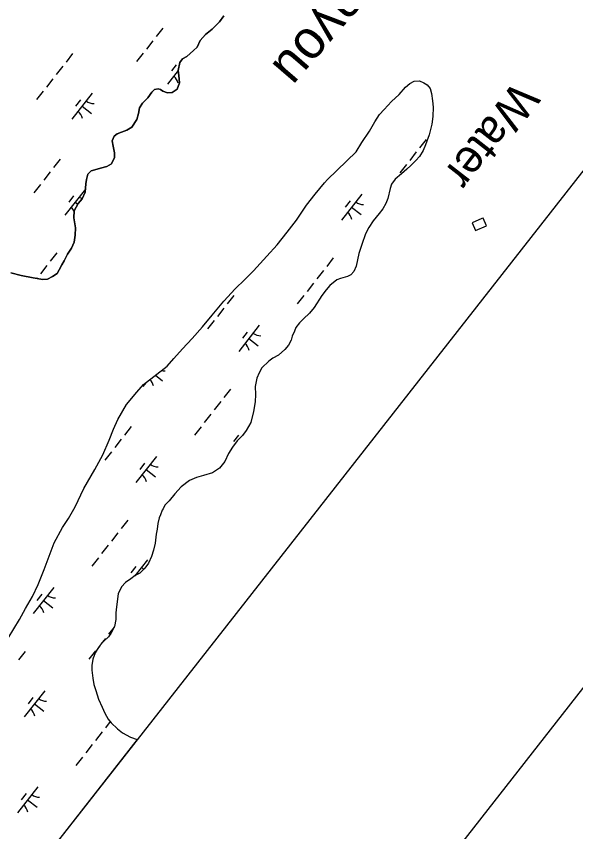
# Model space of a CAD drawing. Extents: x 3896831 to 3918110, y 171006 to 193349.
# Drawn here: x 3906732 to 3907575, y 172821 to 174050 of the extents above; entities that cross this region are included whole.
import ezdxf

# ---------------------------------------------------------------- set-up
doc = ezdxf.new("R2010")
doc.units = 0
for name, color, linetype in [('V-ANNO-SYMB', 7, 'Continuous'), ('V-CHAN-DOCK', 7, 'Continuous'), ('V-GRID-FRAM', 7, 'Continuous'), ('V-RIVR-IDEN', 7, 'Continuous'), ('V-TOPO-SHOR', 7, 'Continuous'), ('V-WETL-SWMP', 7, 'Continuous')]:
    doc.layers.add(name, color=color, linetype=linetype)

msp = doc.modelspace()

# ---------------------------------------------------------------- linework, layer by layer
at = {"layer": 'V-ANNO-SYMB'}
msp.add_lwpolyline([(3907767.9, 191844.4), (3897563.8, 178825.1), (3906582.3, 171756.8), (3916786.3, 184776.1), (3907767.9, 191844.4)], dxfattribs=at)
at = {"layer": 'V-CHAN-DOCK'}
msp.add_lwpolyline([(3907433.8, 173745), (3907419.1, 173738.7), (3907424.1, 173726.9), (3907440.7, 173734), (3907435.7, 173745.8)], close=True, dxfattribs=at)
at = {"layer": 'V-GRID-FRAM'}
msp.add_lwpolyline([(3916044.9, 184610), (3906752.8, 172754.1), (3900055.1, 177809.8), (3909313.3, 189695.8), (3916044.9, 184610)], dxfattribs=at)
at = {"layer": 'V-TOPO-SHOR'}
for points in [[(3906890.5, 173875.2), (3906898.4, 173878), (3906906.3, 173882.9), (3906913.8, 173894.5), (3906916.4, 173903.2), (3906917.9, 173912), (3906922.2, 173918.8), (3906930.1, 173927.2), (3906936.4, 173935.6), (3906940.3, 173939.6), (3906945.9, 173940.5), (3906949.4, 173939.3), (3906953, 173937), (3906959.8, 173934.3), (3906967, 173935.2), (3906974.5, 173940), (3906977.9, 173949.6), (3906977, 173960.7), (3906976.1, 173968.2), (3906978.4, 173980.2), (3906982.7, 173985.8), (3906989, 173989), (3906999.3, 173998.3), (3907004.4, 174003.1), (3907009, 174013.5), (3907017.3, 174022.3), (3907027.1, 174030.3), (3907038.5, 174041.6), (3907044.8, 174050.4)], [(3906898.2, 173464.9), (3906913.8, 173483.7), (3906924, 173495.3), (3906943.6, 173510.5), (3906959.3, 173522.9), (3906969.5, 173534.5), (3906982.4, 173548.9), (3906996.9, 173564.5), (3907012.9, 173582.1), (3907027.4, 173599.3), (3907044.6, 173620.8), (3907061.8, 173639.2), (3907076.3, 173653.2), (3907089.6, 173666.4), (3907109.6, 173688.4), (3907125.2, 173705.6), (3907140.5, 173724.4), (3907154.5, 173742.7), (3907169.3, 173765.1), (3907182.6, 173781.8), (3907196.7, 173799), (3907201, 173803.8), (3907244.1, 173845.4), (3907252.7, 173859.8), (3907264.4, 173876.5), (3907272.5, 173890.8), (3907279.6, 173902), (3907286.2, 173909.6), (3907297.6, 173921.2), (3907308.9, 173932), (3907318.7, 173943.2), (3907325, 173948.8), (3907331.7, 173952), (3907339.6, 173952.5), (3907346.4, 173949.8), (3907351.5, 173946.3), (3907355.9, 173941.2), (3907358, 173933.3), (3907359.3, 173922.6), (3907360.2, 173912.7), (3907360, 173898.9), (3907358.5, 173887.4), (3907354.3, 173871.1), (3907348.9, 173856.4), (3907345.4, 173847.7), (3907339.6, 173838.5), (3907334.1, 173832.5), (3907326.7, 173824.9), (3907320.8, 173819.7), (3907312.6, 173812.5), (3907303.1, 173804.5), (3907297.3, 173796.9), (3907295.4, 173790.5), (3907292, 173775.4), (3907288.9, 173767.9), (3907284.6, 173759.5), (3907279.1, 173752.7), (3907269.8, 173741.6), (3907263.1, 173731.6), (3907258.1, 173722), (3907252.7, 173705.8), (3907248.5, 173692.6), (3907246.2, 173682.7), (3907244.3, 173673.6), (3907240.9, 173665.2), (3907236.2, 173660.1), (3907231, 173658), (3907220.8, 173654.7), (3907214.9, 173652.7), (3907204.7, 173644.3), (3907199.2, 173637.9), (3907192.6, 173629.1), (3907180.9, 173611.2), (3907173.8, 173602.4), (3907164.8, 173594), (3907158.9, 173588), (3907153.5, 173581.2), (3907151.1, 173575.6), (3907147.7, 173568.1), (3907146.1, 173562.1), (3907142.3, 173554.6), (3907136.8, 173547.8), (3907127.4, 173539.4), (3907118.7, 173534.9), (3907112.8, 173530.1), (3907102.2, 173520.1), (3907098, 173512.5), (3907094.5, 173504.6), (3907091.9, 173491.9), (3907092.4, 173480), (3907092.1, 173468.9), (3907089.5, 173454.6), (3907085.3, 173438), (3907078.3, 173426), (3907072.8, 173418.4), (3907065, 173410), (3907058, 173400.9), (3907052.1, 173391.3), (3907046.3, 173379), (3907038.5, 173369), (3907027.9, 173362.1)], [(3906723.9, 173663.3), (3906739.5, 173659.1), (3906757.4, 173655.7), (3906772.1, 173653.4), (3906779.2, 173653.9), (3906786.7, 173657.6), (3906793.8, 173662.4), (3906796.6, 173667.6), (3906800.9, 173675.6), (3906804.4, 173681.6), (3906809.4, 173691.2), (3906815.3, 173700.4), (3906819.2, 173709.6), (3906820.6, 173720.3), (3906821.3, 173731), (3906818.8, 173746.1), (3906819.5, 173756.8), (3906825.3, 173768), (3906831.2, 173774.8), (3906835.9, 173784.8), (3906836.9, 173797.5), (3906837.6, 173803.9), (3906839.9, 173811.9), (3906844.7, 173817.1), (3906850.2, 173818.7), (3906858.9, 173820.8), (3906868.4, 173823.3), (3906875.5, 173827.3), (3906880.2, 173836.9), (3906880.1, 173844.1), (3906878, 173854), (3906876.4, 173862.3), (3906879.5, 173869.1), (3906884.2, 173872.7), (3906890.5, 173875.2)], [(3906719.7, 173113.1), (3906736.9, 173141), (3906745.8, 173157.7), (3906756.3, 173175.6), (3906765.2, 173193.9), (3906774.1, 173216.6), (3906781.4, 173236.4), (3906789.1, 173256.7), (3906801.5, 173279.8), (3906810.9, 173293.4), (3906820.6, 173310.9), (3906833.8, 173338.3), (3906850.5, 173367), (3906862.5, 173388.9), (3906872.2, 173411.2), (3906878.7, 173427.9), (3906885.3, 173442.6), (3906898.2, 173464.9)], [(3907027.9, 173362.1), (3907014.1, 173358), (3907003.4, 173355.2), (3906993.2, 173350.7), (3906980.6, 173340.7), (3906971.2, 173330.3), (3906962.6, 173319.9), (3906956, 173313.1), (3906953.2, 173307.9), (3906952.1, 173305.9), (3906949.4, 173298.8), (3906947.5, 173294), (3906945.6, 173285.7), (3906944.5, 173277.3), (3906943, 173269.4), (3906941.1, 173255.9), (3906939, 173245.6), (3906936, 173236.1), (3906931.4, 173226.1), (3906925.9, 173218.2), (3906918.1, 173210.9), (3906911.4, 173207.3), (3906904.7, 173202.5), (3906896.8, 173196.9), (3906890.6, 173190.1), (3906885.5, 173179.7), (3906882.6, 173155.9), (3906882.3, 173150.4), (3906882, 173141.3), (3906880.1, 173130.6), (3906874.7, 173120.2), (3906870.8, 173115), (3906864.1, 173108.6), (3906858.2, 173102.6), (3906854, 173095.9), (3906850.8, 173090.7), (3906847.4, 173081.5), (3906845.9, 173071.6), (3906846, 173064.5), (3906847.3, 173052.6), (3906849, 173043.2), (3906851.8, 173034.1), (3906855.9, 173021.1), (3906861.6, 173008.9), (3906865.3, 172999.8), (3906870.5, 172990.7), (3906874.9, 172985.6), (3906884.5, 172976.6), (3906892.1, 172970.4), (3906904, 172963.8), (3906914, 172960.3), (3906914.3, 172960.2)]]:
    msp.add_lwpolyline(points, dxfattribs=at)
at = {"layer": 'V-WETL-SWMP'}
for p, q in [((3907044.8, 174050.4), (3907038.5, 174041.6)), ((3907038.5, 174041.6), (3907027.1, 174030.3)), ((3906952.8, 174031.9), (3906942.9, 174019.3)), ((3907027.1, 174030.3), (3907017.3, 174022.3)), ((3906938, 174013), (3906928.1, 174000.4)), ((3907009, 174013.5), (3907004.4, 174003.1)), ((3907017.3, 174022.3), (3907009, 174013.5)), ((3907004.4, 174003.1), (3906999.3, 173998.3)), ((3906816.9, 173993.5), (3906807.1, 173980.9)), ((3906923.2, 173994.1), (3906913.3, 173981.5)), ((3906989, 173989), (3906982.7, 173985.8)), ((3906999.3, 173998.3), (3906989, 173989)), ((3906973.2, 173976.9), (3906965.8, 173967.4)), ((3906978.4, 173980.2), (3906976.1, 173968.2)), ((3906982.7, 173985.8), (3906978.4, 173980.2)), ((3906802.1, 173974.6), (3906792.2, 173962)), ((3906976.2, 173968.1), (3906960.1, 173947.7)), ((3906975.6, 173967.4), (3906976.3, 173966.8)), ((3906976.1, 173968.2), (3906977, 173960.7)), ((3906787.3, 173955.7), (3906777.4, 173943.1)), ((3906977, 173960.7), (3906977.9, 173949.6)), ((3907325, 173948.8), (3907331.7, 173952)), ((3907331.7, 173952), (3907339.6, 173952.5)), ((3907339.6, 173952.5), (3907346.4, 173949.8)), ((3906940.3, 173939.6), (3906936.4, 173935.6)), ((3906945.9, 173940.5), (3906940.3, 173939.6)), ((3906949.4, 173939.3), (3906945.9, 173940.5)), ((3906953, 173937), (3906949.4, 173939.3)), ((3906974.5, 173940), (3906967, 173935.2)), ((3906977.9, 173949.6), (3906974.5, 173940)), ((3907308.9, 173932), (3907318.7, 173943.2)), ((3907318.7, 173943.2), (3907325, 173948.8)), ((3907346.4, 173949.8), (3907351.5, 173946.3)), ((3907351.5, 173946.3), (3907355.9, 173941.2)), ((3907355.9, 173941.2), (3907358, 173933.3)), ((3906772.5, 173936.8), (3906762.6, 173924.2)), ((3906846.6, 173934.1), (3906815.8, 173894.7)), ((3906930.1, 173927.2), (3906922.2, 173918.8)), ((3906936.4, 173935.6), (3906930.1, 173927.2)), ((3906959.8, 173934.3), (3906953, 173937)), ((3906967, 173935.2), (3906959.8, 173934.3)), ((3907297.6, 173921.2), (3907308.9, 173932)), ((3907358, 173933.3), (3907359.3, 173922.6)), ((3906828.8, 173923.9), (3906821.4, 173914.5)), ((3906831.2, 173914.4), (3906845.4, 173903.3)), ((3906922.2, 173918.8), (3906917.9, 173912)), ((3907286.2, 173909.6), (3907297.6, 173921.2)), ((3907359.3, 173922.6), (3907360.2, 173912.7)), ((3906916.4, 173903.2), (3906913.8, 173894.5)), ((3906917.9, 173912), (3906916.4, 173903.2)), ((3907272.5, 173890.8), (3907279.6, 173902)), ((3907279.6, 173902), (3907286.2, 173909.6)), ((3907360.2, 173912.7), (3907360, 173898.9)), ((3906913.8, 173894.5), (3906906.3, 173882.9)), ((3907264.4, 173876.5), (3907272.5, 173890.8)), ((3907360, 173898.9), (3907358.5, 173887.4)), ((3906898.4, 173878), (3906890.5, 173875.2)), ((3906906.3, 173882.9), (3906898.4, 173878)), ((3907358.5, 173887.4), (3907354.3, 173871.1)), ((3906879.5, 173869.1), (3906876.4, 173862.3)), ((3906884.2, 173872.7), (3906879.5, 173869.1)), ((3906890.5, 173875.2), (3906884.2, 173872.7)), ((3907252.7, 173859.8), (3907264.4, 173876.5)), ((3907349.7, 173864.3), (3907339.8, 173851.7)), ((3907354.3, 173871.1), (3907348.9, 173856.4)), ((3906876.4, 173862.3), (3906878, 173854)), ((3906878, 173854), (3906880.1, 173844.1)), ((3907244.1, 173845.4), (3907252.7, 173859.8)), ((3907348.9, 173856.4), (3907345.4, 173847.7)), ((3906880.1, 173844.1), (3906880.2, 173836.9)), ((3907201, 173803.8), (3907244.1, 173845.4)), ((3907334.9, 173845.4), (3907325, 173832.8)), ((3907345.4, 173847.7), (3907339.6, 173838.5)), ((3906798, 173834.4), (3906788.1, 173821.8)), ((3906880.2, 173836.9), (3906875.5, 173827.3)), ((3907334.1, 173832.5), (3907326.7, 173824.9)), ((3907339.6, 173838.5), (3907334.1, 173832.5)), ((3906783.2, 173815.5), (3906773.3, 173802.9)), ((3906844.7, 173817.1), (3906839.9, 173811.9)), ((3906850.2, 173818.7), (3906844.7, 173817.1)), ((3906858.9, 173820.8), (3906850.2, 173818.7)), ((3906868.4, 173823.3), (3906858.9, 173820.8)), ((3906875.5, 173827.3), (3906868.4, 173823.3)), ((3907320.1, 173826.5), (3907310.2, 173813.9)), ((3907320.8, 173819.7), (3907312.6, 173812.5)), ((3907326.7, 173824.9), (3907320.8, 173819.7)), ((3906837.6, 173803.9), (3906836.9, 173797.5)), ((3906839.9, 173811.9), (3906837.6, 173803.9)), ((3907196.7, 173799), (3907201, 173803.8)), ((3907303.1, 173804.5), (3907297.3, 173796.9)), ((3907312.6, 173812.5), (3907303.1, 173804.5)), ((3906768.4, 173796.6), (3906758.5, 173784)), ((3906836.9, 173797.5), (3906835.9, 173784.8)), ((3907182.6, 173781.8), (3907196.7, 173799)), ((3907297.3, 173796.9), (3907295.4, 173790.5)), ((3906836.2, 173789.5), (3906805.3, 173750.2)), ((3906818.4, 173779.3), (3906811, 173769.9)), ((3906835.9, 173784.8), (3906831.2, 173774.8)), ((3907169.4, 173765.1), (3907182.6, 173781.8)), ((3907252.8, 173781.8), (3907222, 173742.5)), ((3907295.4, 173790.5), (3907292, 173775.4)), ((3906825.3, 173768), (3906819.5, 173756.8)), ((3906820.7, 173769.9), (3906824.7, 173766.8)), ((3906831.2, 173774.8), (3906825.3, 173768)), ((3907235, 173771.6), (3907227.6, 173762.2)), ((3907288.9, 173767.9), (3907284.6, 173759.5)), ((3907292, 173775.4), (3907288.9, 173767.9)), ((3906819.5, 173756.8), (3906818.8, 173746.1)), ((3907154.5, 173742.7), (3907169.4, 173765.1)), ((3907237.4, 173762.2), (3907251.6, 173751.1)), ((3907284.6, 173759.5), (3907279.1, 173752.7)), ((3906818.8, 173746.1), (3906821.3, 173731)), ((3907140.5, 173724.4), (3907154.5, 173742.7)), ((3907269.8, 173741.6), (3907263.1, 173731.6)), ((3907279.1, 173752.7), (3907269.8, 173741.6)), ((3906821.3, 173731), (3906820.6, 173720.3)), ((3907263.1, 173731.6), (3907258.1, 173722)), ((3906820.6, 173720.3), (3906819.2, 173709.6)), ((3907125.2, 173705.6), (3907140.5, 173724.4)), ((3907258.1, 173722), (3907252.7, 173705.8)), ((3906819.2, 173709.6), (3906815.3, 173700.4)), ((3907109.6, 173688.4), (3907125.2, 173705.6)), ((3907252.7, 173705.8), (3907248.5, 173692.6)), ((3906793, 173693.4), (3906783.2, 173680.8)), ((3906815.3, 173700.4), (3906809.4, 173691.2)), ((3907248.5, 173692.6), (3907246.2, 173682.7)), ((3906804.4, 173681.6), (3906800.9, 173675.6)), ((3906809.4, 173691.2), (3906804.4, 173681.6)), ((3907089.6, 173666.4), (3907109.6, 173688.4)), ((3907209.7, 173685.7), (3907199.8, 173673.1)), ((3907246.2, 173682.7), (3907244.3, 173673.6)), ((3906778.2, 173674.5), (3906768.4, 173661.9)), ((3906800.9, 173675.6), (3906796.6, 173667.6)), ((3907244.3, 173673.6), (3907240.9, 173665.2)), ((3906739.5, 173659.1), (3906723.9, 173663.3)), ((3906757.4, 173655.7), (3906739.5, 173659.1)), ((3906772.1, 173653.4), (3906757.4, 173655.7)), ((3906763.4, 173655.6), (3906762.8, 173654.8)), ((3906786.7, 173657.6), (3906779.2, 173653.9)), ((3906793.8, 173662.4), (3906786.7, 173657.6)), ((3906796.6, 173667.6), (3906793.8, 173662.4)), ((3907076.3, 173653.2), (3907089.6, 173666.4)), ((3907194.9, 173666.8), (3907185, 173654.2)), ((3907231, 173658), (3907220.8, 173654.7)), ((3907236.2, 173660.1), (3907231, 173658)), ((3907240.9, 173665.2), (3907236.2, 173660.1)), ((3906779.2, 173653.9), (3906772.1, 173653.4)), ((3907061.8, 173639.2), (3907076.3, 173653.2)), ((3907180.1, 173647.9), (3907170.2, 173635.3)), ((3907204.7, 173644.3), (3907199.2, 173637.9)), ((3907214.9, 173652.7), (3907204.7, 173644.3)), ((3907220.8, 173654.7), (3907214.9, 173652.7)), ((3907044.6, 173620.8), (3907061.8, 173639.2)), ((3907199.2, 173637.9), (3907192.6, 173629.1)), ((3907027.4, 173599.3), (3907044.6, 173620.8)), ((3907059.8, 173629.1), (3907049.9, 173616.5)), ((3907165.3, 173629), (3907155.4, 173616.4)), ((3907192.6, 173629.1), (3907180.9, 173611.2)), ((3907045, 173610.2), (3907035.1, 173597.7)), ((3907180.9, 173611.2), (3907173.8, 173602.4)), ((3907012.9, 173582.1), (3907027.4, 173599.3)), ((3907173.8, 173602.4), (3907164.8, 173594)), ((3906996.9, 173564.5), (3907012.9, 173582.1)), ((3907030.2, 173591.4), (3907020.3, 173578.8)), ((3907098, 173584.3), (3907067.2, 173545)), ((3907158.9, 173588), (3907153.5, 173581.2)), ((3907164.8, 173594), (3907158.9, 173588)), ((3907080.2, 173574.1), (3907072.8, 173564.7)), ((3907151.1, 173575.6), (3907147.7, 173568.1)), ((3907153.5, 173581.2), (3907151.1, 173575.6)), ((3906982.4, 173548.9), (3906996.9, 173564.5)), ((3907082.6, 173564.6), (3907096.8, 173553.5)), ((3907146.1, 173562.1), (3907142.3, 173554.6)), ((3907147.7, 173568.1), (3907146.1, 173562.1)), ((3906969.5, 173534.5), (3906982.4, 173548.9)), ((3907136.8, 173547.8), (3907127.4, 173539.4)), ((3907142.3, 173554.6), (3907136.8, 173547.8)), ((3906959.3, 173522.9), (3906969.5, 173534.5)), ((3907118.7, 173534.9), (3907112.8, 173530.1)), ((3907127.4, 173539.4), (3907118.7, 173534.9)), ((3906943.6, 173510.5), (3906959.3, 173522.9)), ((3907112.8, 173530.1), (3907102.2, 173520.1)), ((3906924, 173495.3), (3906943.6, 173510.5)), ((3906941.7, 173509), (3906952.4, 173500.6)), ((3907098, 173512.5), (3907094.5, 173504.6)), ((3907102.2, 173520.1), (3907098, 173512.5)), ((3906927.6, 173498.1), (3906922.8, 173492)), ((3907094.5, 173504.6), (3907091.9, 173491.9)), ((3906898.2, 173464.9), (3906913.8, 173483.7)), ((3906913.8, 173483.7), (3906924, 173495.3)), ((3907054.9, 173488.2), (3907045, 173475.6)), ((3907091.9, 173491.9), (3907092.4, 173480)), ((3907092.4, 173480), (3907092.1, 173468.9)), ((3906885.3, 173442.6), (3906898.2, 173464.9)), ((3907040.1, 173469.3), (3907030.2, 173456.7)), ((3907092.1, 173468.9), (3907089.5, 173454.6)), ((3907025.3, 173450.4), (3907015.4, 173437.8)), ((3907089.5, 173454.6), (3907085.3, 173438)), ((3906878.7, 173427.9), (3906885.3, 173442.6)), ((3907085.3, 173438), (3907078.3, 173426)), ((3906872.2, 173411.2), (3906878.7, 173427.9)), ((3906905, 173431.6), (3906895.1, 173419)), ((3907010.5, 173431.5), (3907000.6, 173418.9)), ((3907078.3, 173426), (3907072.8, 173418.4)), ((3906862.5, 173388.9), (3906872.2, 173411.2)), ((3906890.2, 173412.7), (3906880.3, 173400.1)), ((3907065, 173410), (3907058, 173400.9)), ((3907066.8, 173418.6), (3907059.4, 173409.1)), ((3907072.8, 173418.4), (3907065, 173410)), ((3907058, 173400.9), (3907052.1, 173391.3)), ((3906850.5, 173367), (3906862.5, 173388.9)), ((3906875.4, 173393.8), (3906865.5, 173381.2)), ((3906943.2, 173386.8), (3906912.4, 173347.4)), ((3907052.1, 173391.3), (3907046.3, 173379)), ((3906925.4, 173376.6), (3906918, 173367.2)), ((3907046.3, 173379), (3907038.5, 173369)), ((3906833.8, 173338.3), (3906850.5, 173367)), ((3906927.8, 173367.1), (3906941.9, 173356)), ((3907027.9, 173362.1), (3907014.1, 173358)), ((3907038.5, 173369), (3907027.9, 173362.1)), ((3906993.2, 173350.7), (3906980.6, 173340.7)), ((3907003.4, 173355.2), (3906993.2, 173350.7)), ((3907014.1, 173358), (3907003.4, 173355.2)), ((3906820.6, 173310.9), (3906833.8, 173338.3)), ((3906980.6, 173340.7), (3906971.2, 173330.3)), ((3906971.2, 173330.3), (3906962.6, 173319.9)), ((3906956, 173313.1), (3906953.2, 173307.9)), ((3906962.6, 173319.9), (3906956, 173313.1)), ((3906810.9, 173293.4), (3906820.6, 173310.9)), ((3906952.1, 173305.9), (3906949.4, 173298.8)), ((3906953.2, 173307.9), (3906952.1, 173305.9)), ((3906801.5, 173279.8), (3906810.9, 173293.4)), ((3906900.1, 173290.6), (3906890.2, 173278)), ((3906947.5, 173294), (3906945.6, 173285.7)), ((3906949.4, 173298.8), (3906947.5, 173294)), ((3906789.1, 173256.7), (3906801.5, 173279.8)), ((3906944.5, 173277.3), (3906943, 173269.4)), ((3906945.6, 173285.7), (3906944.5, 173277.3)), ((3906885.3, 173271.7), (3906875.4, 173259.2)), ((3906943, 173269.4), (3906941.1, 173255.9)), ((3906781.4, 173236.4), (3906789.1, 173256.7)), ((3906870.5, 173252.9), (3906860.6, 173240.3)), ((3906941.1, 173255.9), (3906939, 173245.6)), ((3906939, 173245.6), (3906936, 173236.1)), ((3906774.1, 173216.6), (3906781.4, 173236.4)), ((3906855.7, 173234), (3906845.8, 173221.4)), ((3906929.8, 173231.2), (3906910.6, 173206.7)), ((3906931.4, 173226.1), (3906925.9, 173218.2)), ((3906936, 173236.1), (3906931.4, 173226.1)), ((3906765.2, 173193.9), (3906774.1, 173216.6)), ((3906912, 173221), (3906904.6, 173211.6)), ((3906925.9, 173218.2), (3906918.1, 173210.9)), ((3906904.7, 173202.5), (3906896.8, 173196.9)), ((3906911.4, 173207.3), (3906904.7, 173202.5)), ((3906918.1, 173210.9), (3906911.4, 173207.3)), ((3906914.4, 173211.6), (3906916.3, 173210)), ((3906756.3, 173175.6), (3906765.2, 173193.9)), ((3906788.4, 173189.3), (3906757.6, 173149.9)), ((3906890.6, 173190.1), (3906885.5, 173179.7)), ((3906896.8, 173196.9), (3906890.6, 173190.1)), ((3906770.6, 173179.1), (3906763.2, 173169.6)), ((3906885.5, 173179.7), (3906882.6, 173155.9)), ((3906745.8, 173157.7), (3906756.3, 173175.6)), ((3906773, 173169.6), (3906787.1, 173158.5)), ((3906736.9, 173141), (3906745.8, 173157.7)), ((3906882.6, 173155.9), (3906882.3, 173150.4)), ((3906719.7, 173113.1), (3906736.9, 173141)), ((3906882, 173141.3), (3906880.1, 173130.6)), ((3906882.3, 173150.4), (3906882, 173141.3)), ((3906879.6, 173129.5), (3906871.2, 173118.9)), ((3906880.1, 173130.6), (3906874.7, 173120.2)), ((3906870.8, 173115), (3906864.1, 173108.6)), ((3906874.7, 173120.2), (3906870.8, 173115)), ((3906864.1, 173108.6), (3906858.2, 173102.6)), ((3906866.3, 173112.6), (3906859.5, 173103.9)), ((3906745.3, 173093.1), (3906735.4, 173080.5)), ((3906851.5, 173093.7), (3906841.6, 173081.1)), ((3906850.8, 173090.7), (3906847.4, 173081.5)), ((3906854, 173095.9), (3906850.8, 173090.7)), ((3906858.2, 173102.6), (3906854, 173095.9)), ((3906857.2, 173101), (3906856.4, 173100)), ((3906847.4, 173081.5), (3906845.9, 173071.6)), ((3906845.9, 173071.6), (3906846, 173064.5)), ((3906846, 173064.5), (3906847.3, 173052.6)), ((3906847.3, 173052.6), (3906849, 173043.2)), ((3906849, 173043.2), (3906851.8, 173034.1)), ((3906775, 173033.7), (3906744.1, 172994.4)), ((3906851.8, 173034.1), (3906855.9, 173021.1)), ((3906757.2, 173023.5), (3906749.8, 173014.1)), ((3906855.9, 173021.1), (3906861.6, 173008.9)), ((3906759.6, 173014), (3906773.7, 173002.9)), ((3906861.6, 173008.9), (3906865.3, 172999.8)), ((3906865.3, 172999.8), (3906870.5, 172990.7)), ((3906873.6, 172987.2), (3906866.3, 172977.9)), ((3906870.5, 172990.7), (3906874.9, 172985.6)), ((3906874.9, 172985.6), (3906884.5, 172976.6)), ((3906861.4, 172971.6), (3906851.5, 172959)), ((3906884.5, 172976.6), (3906892.1, 172970.4)), ((3906892.1, 172970.4), (3906904, 172963.8)), ((3906914.3, 172960.2), (3906752.8, 172754.1)), ((3906904, 172963.8), (3906914, 172960.3)), ((3906914, 172960.3), (3906914.3, 172960.2)), ((3906846.6, 172952.7), (3906836.7, 172940.1)), ((3906831.8, 172933.8), (3906821.9, 172921.2)), ((3906764.5, 172889.2), (3906733.7, 172849.8)), ((3906746.7, 172879), (3906739.3, 172869.5)), ((3906749.1, 172869.5), (3906763.3, 172858.4))]:
    msp.add_line(p, q, dxfattribs=at)
for centre, start, end in [((3906958.7, 173945.5), 11.1403, 52.6839), ((3906848.4, 173936), 231.1403, 272.6839), ((3906814.4, 173892.5), 11.1403, 52.6839), ((3906838, 173791.5), 231.1403, 247.8722), ((3907254.6, 173783.8), 231.1403, 272.6839), ((3906803.9, 173748), 28.1506, 52.6839), ((3907220.5, 173740.3), 11.1403, 52.6839), ((3907099.8, 173586.2), 231.1403, 272.6839), ((3907065.7, 173542.8), 11.1403, 52.6839), ((3906955.5, 173533.3), 254.8463, 272.6839), ((3906921.4, 173489.8), 11.1403, 46.7804), ((3906945, 173388.7), 231.1403, 272.6839), ((3906910.9, 173345.2), 11.1403, 52.6839), ((3906931.6, 173233.1), 231.1403, 246.7061), ((3906790.2, 173191.2), 231.1403, 272.6839), ((3906756.1, 173147.7), 11.1403, 52.6839), ((3906776.8, 173035.6), 231.1403, 272.6839), ((3906742.7, 172992.2), 11.1403, 52.6839), ((3906766.3, 172891.1), 231.1403, 272.6839), ((3906732.2, 172847.6), 11.1403, 52.6839)]:
    msp.add_arc(centre, 17.6, start, end, dxfattribs=at)

# ---------------------------------------------------------------- texts
at = {"layer": 'V-RIVR-IDEN'}
for s, height, rotation, p in [('Bayou', 58, 229.2495, (3907258.4, 174141.1)), ('Water', 50, 232.0843, (3907484, 173954.3))]:
    msp.add_text(s, height=height, rotation=rotation, dxfattribs=at).set_placement(p)

doc.saveas('drawing.dxf')
